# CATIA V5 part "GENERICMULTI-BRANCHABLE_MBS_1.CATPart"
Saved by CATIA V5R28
Part number: GENERICMULTI-BRANCHABLE_MBS_1
Revision: ---
Publications: "SegmentExtremity.1", "SegmentExtremity.2", "ElecLogTerm.1", "Flexible Curve.1", "Point.6", "SegmentExtremity.3", "SegmentExtremity.4", "ElecLogTerm.2", "Flexible Curve.2", "Point.10", "SegmentExtremity.5", "SegmentExtremity.6", "ElecLogTerm.3", "Flexible Curve.3", "Point.12", "SegmentExtremity.7", "SegmentExtremity.8", "ElecLogTerm.4", "Flexible Curve.4", "Point.20", "SegmentExtremity.9", "SegmentExtremity.10", "ElecLogTerm.5", "Flexible Curve.5", "Point.22", "SegmentExtremity.11", "SegmentExtremity.12", "ElecLogTerm.6", "Flexible Curve.6", "SegmentExtremity.13", "SegmentExtremity.14", "ElecLogTerm.7", "Flexible Curve.7", "Point.31", "SegmentExtremity.15", "SegmentExtremity.16", "ElecLogTerm.8", "Flexible Curve.8", "Point.47", "SegmentExtremity.17", "SegmentExtremity.18", "ElecLogTerm.9", "Flexible Curve.9", "Point.49", "SegmentExtremity.19", "SegmentExtremity.20", "ElecLogTerm.10", "Flexible Curve.10", "CPoint.52", "SegmentExtremity.21", "SegmentExtremity.22", "ElecLogTerm.11", "Flexible Curve.11", "Point.65", "SegmentExtremity.23", "SegmentExtremity.24", "ElecLogTerm.12", "Flexible Curve.12", "Point.70", "SegmentExtremity.25", "SegmentExtremity.26", "ElecLogTerm.13", "Flexible Curve.13", "SegmentExtremity.27", "SegmentExtremity.28", "ElecLogTerm.14", "Flexible Curve.14", "SegmentExtremity.29", "SegmentExtremity.30", "ElecLogTerm.15", "Flexible Curve.15", "Point.98", "SegmentExtremity.31", "SegmentExtremity.32", "ElecLogTerm.16", "Flexible Curve.16", "Point.104", "SegmentExtremity.33", "SegmentExtremity.34", "ElecLogTerm.17", "Flexible Curve.17", "Point.106", "SegmentExtremity.35", "SegmentExtremity.36", "ElecLogTerm.18", "Flexible Curve.18", "Point.109", "SegmentExtremity.37", "SegmentExtremity.38", "ElecLogTerm.19", "Flexible Curve.19", "Point.118", "SegmentExtremity.39", "SegmentExtremity.40", "ElecLogTerm.20", "Flexible Curve.20", "Point.122", "SegmentExtremity.41", "SegmentExtremity.42", "ElecLogTerm.21", "Flexible Curve.21", "Point.127", "SegmentExtremity.43", "SegmentExtremity.44", "ElecLogTerm.22", "Flexible Curve.22", "Point.132", "SegmentExtremity.45", "SegmentExtremity.46", "ElecLogTerm.23", "Flexible Curve.23", "Point.137", "SegmentExtremity.47", "SegmentExtremity.48", "ElecLogTerm.24", "Flexible Curve.24", "SegmentExtremity.49", "SegmentExtremity.50", "ElecLogTerm.25", "Flexible Curve.25", "SegmentExtremity.51", "SegmentExtremity.52", "ElecLogTerm.26", "Flexible Curve.26", "Point.146", "Point.175", "SegmentExtremity.53", "SegmentExtremity.54", "Flexible Curve.27", "Point.192", "SegmentExtremity.55", "SegmentExtremity.56", "ElecLogTerm.28", "Flexible Curve.28", "Point.205", "SegmentExtremity.57", "SegmentExtremity.58", "ElecLogTerm.29", "Flexible Curve.29", "Point.210", "SegmentExtremity.59", "SegmentExtremity.60", "ElecLogTerm.30", "Flexible Curve.30", "SegmentExtremity.61", "SegmentExtremity.62", "ElecLogTerm.31", "Flexible Curve.31", "SegmentExtremity.63", "SegmentExtremity.64", "ElecLogTerm.32", "Flexible Curve.32", "Point.222", "Point.227", "SegmentExtremity.65", "SegmentExtremity.66", "ElecLogTerm.33", "Flexible Curve.33", "Point.238", "SegmentExtremity.67", "SegmentExtremity.68", "ElecLogTerm.34", "Flexible Curve.34", "Point.240", "Point.245", "SegmentExtremity.69", "SegmentExtremity.70", "ElecLogTerm.35", "Flexible Curve.35", "Point.250", "SegmentExtremity.71", "SegmentExtremity.72", "ElecLogTerm.36", "Flexible Curve.36", "Point.258", "SegmentExtremity.73", "SegmentExtremity.74", "ElecLogTerm.37", "Flexible Curve.37", "Point.269", "SegmentExtremity.75", "SegmentExtremity.76", "ElecLogTerm.38", "Flexible Curve.38", "Point.276", "SegmentExtremity.77", "SegmentExtremity.78", "ElecLogTerm.39", "Flexible Curve.39", "Point.278", "Point.281", "SegmentExtremity.79", "SegmentExtremity.80", "ElecLogTerm.40", "Flexible Curve.40", "Point.286", "SegmentExtremity.81", "SegmentExtremity.82", "ElecLogTerm.41", "Flexible Curve.41", "Point.291", "SegmentExtremity.83", "SegmentExtremity.84", "ElecLogTerm.42", "Flexible Curve.42", "SegmentExtremity.85", "SegmentExtremity.86", "ElecLogTerm.43", "Flexible Curve.43", "SegmentExtremity.87", "SegmentExtremity.88", "ElecLogTerm.44", "Flexible Curve.44", "SegmentExtremity.89", "SegmentExtremity.90", "ElecLogTerm.45", "Flexible Curve.45", "SegmentExtremity.91", "SegmentExtremity.92", "ElecLogTerm.46", "Flexible Curve.46", "SegmentExtremity.93", "SegmentExtremity.94", "ElecLogTerm.47", "Flexible Curve.47", "Point.309", "SegmentExtremity.95", "SegmentExtremity.96", "ElecLogTerm.48", "Flexible Curve.48", "SegmentExtremity.97", "SegmentExtremity.98", "ElecLogTerm.49", "Flexible Curve.49", "CPoint.315", "SegmentExtremity.99", "SegmentExtremity.100", "ElecLogTerm.50", "Flexible Curve.50", "SegmentExtremity.101", "SegmentExtremity.102", "ElecLogTerm.51", "Flexible Curve.51", "SegmentExtremity.105", "SegmentExtremity.106", "ElecLogTerm.53", "Flexible Curve.53", "Point.329", "SegmentExtremity.107", "SegmentExtremity.108", "ElecLogTerm.54", "Flexible Curve.54", "SegmentExtremity.109", "SegmentExtremity.110", "ElecLogTerm.55", "Flexible Curve.55", "Point.358", "BCPRPoint.1", "BCPRPoint.2", "BCPRPoint.3", "BCPRPoint.4", "BCPRPoint.5", "BCPRPoint.6", "BCPRPoint.7", "BCPRPoint.8", "BCPRPoint.9", "BCPRPoint.10", "BCPRPoint.11", "BCPRPoint.12", "BCPRPoint.13", "BCPRPoint.14", "BCPRPoint.15", "Point.376", "Point.377", "Point.378", "Point.379", "Point.380", "Point.381", "Point.382", "Point.383", "Point.384", "Point.385", "Point.386", "Point.387", "Point.388", "Point.389", "Point.390", "Point.391", "Point.392", "Point.393", "Point.394", "Point.395", "Point.396", "Point.397", "Point.398", "Point.399", "Point.400", "Point.401", "Point.402", "Point.403", "Point.404", "Point.405", "Point.406", "Point.407", "Point.408", "Point.409", "Point.410", "Point.411", "Point.412", "Point.413", "Point.414", "Point.415", "Point.416", "Point.417", "Point.418", "Point.419", "Point.420", "Point.421", "Point.422", "Point.423", "Point.424", "Point.425", "Point.426", "ElecLogTerm.58", "SegmentExtremity.117", "SegmentExtremity.118", "ElecLogTerm.59", "Flexible Curve.56", "Point.476", "SegmentExtremity.119", "SegmentExtremity.120", "ElecLogTerm.60", "Flexible Curve.57", "Point.478", "SegmentExtremity.121", "SegmentExtremity.122", "ElecLogTerm.61", "Flexible Curve.58", "Point.480", "SegmentExtremity.123", "SegmentExtremity.124", "ElecLogTerm.62", "Flexible Curve.59", "BCPRPoint_generated(BCP).1", "SegmentExtremity.125", "SegmentExtremity.126", "ElecLogTerm.63", "Flexible Curve.60", "BCPRPoint_generated(BCP).3", "Point.209", "Point.208", "BCPRPoint_generated(BCP).2"
Bounding box of the stored display mesh (mm): x 24808.223 to 28940.348, y -11503.752 to -2466.057, z 3790.857 to 5602.068
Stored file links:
  C:\Users\ajc8720\Documents\BOEING_WORK\0001-2CES\004-AP242\Boeing-Generic_Harness_R3\GENERICMULTI-BRANCHABLE_MBS_1.CATPart
  C:\Users\ajc8720\Documents\BOEING_WORK\0001-2CES\004-AP242\Boeing-Generic_Harness_R3\GENERICBUNDLE_GBN_1.CATProduct
  C:\Users\ajc8720\Documents\BOEING_WORK\0001-2CES\004-AP242\Boeing-Generic_Harness_R3\GENERICMULTI-BRANCHABLE_MBS_2.CATPart
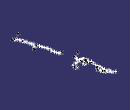
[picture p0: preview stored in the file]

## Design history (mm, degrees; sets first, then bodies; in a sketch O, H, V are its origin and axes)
Sketch1 on {plane type Normal, RefPoint {point type OnCurve, Real 0.5}}, origin (24974.0327, -3716.1791, 3931.1718), H (0.9925, -0.0197, 0.1205), V (0, -0.987, -0.1609)
  circle A1 centre (0, 0) radius 3.429
  point P1 (0, 0)
  reference projected point E1 (0, 0) from {point type OnCurve, Real 0.5}
  radius A1 = 3.429
  distance E1 P1 = 0
ElecRouteBody1
EhiBundleSegmentBody1
Sketch2 on {plane type Normal, RefPoint {point type OnCurve, Real 0.5}}, origin (24996.1011, -3716.6292, 3825.5253), H (0.0885, -0.5472, 0.8323), V (0, -0.8356, -0.5493)
  circle A1 centre (0, 0) radius 2.54
  point P1 (0, 0)
  reference projected point E1 (0, 0) from {point type OnCurve, Real 0.5}
  radius A1 = 2.54
  distance E1 P1 = 0
ElecRouteBody2
EhiBundleSegmentBody2
Sketch3 on {plane type Normal, RefPoint {point type OnCurve, Real 0.5}}, origin (24940.6374, -3680.2606, 3814.3878), H (0.1643, 0.9008, 0.4019), V (0, -0.4074, 0.9132)
  circle A1 centre (0, 0) radius 1.905
  point P1 (0, 0)
  reference projected point E1 (0, 0) from {point type OnCurve, Real 0.5}
  radius A1 = 1.905
  distance E1 P1 = 0
ElecRouteBody3
EhiBundleSegmentBody3
Sketch4 on {plane type Normal, RefPoint {point type OnCurve, Real 0.5}}, origin (25028.8374, -3731.3512, 3879.19), H (0.9078, -0.1558, -0.3893), V (0.0574, 0.9658, -0.2528)
  circle A1 centre (0.6341, 4.1659) radius 2.54
  point P1 (0.6341, 4.1659)
  reference projected point E1 (0.6341, 4.1659) from {point type OnCurve, Real 0.5}
  radius A1 = 2.54
  distance E1 P1 = 0
ElecRouteBody4
EhiBundleSegmentBody4
Sketch5 on {plane type Normal, RefPoint {point type OnCurve, Real 0.5}}, origin (24880.8569, -3717.6101, 3832.7739), H (1, 0, 0), V (0, -0.9945, 0.1045)
  circle A1 centre (0, 0) radius 2.54
  point P1 (0, 0)
  reference projected point E1 (0, 0) from {point type OnCurve, Real 0.5}
  radius A1 = 2.54
  distance E1 P1 = 0
ElecRouteBody5
EhiBundleSegmentBody5
Sketch6 on {plane type Normal, RefPoint {point type OnCurve, Real 0.5}}, origin (24877.0707, -3718.2397, 3795.6193), H (0.9998, -0.0172, -0.0118), V (0, 0.567, -0.8237)
  circle A1 centre (0, 0) radius 1.905
  point P1 (0, 0)
  reference projected point E1 (0, 0) from {point type OnCurve, Real 0.5}
  radius A1 = 1.905
  distance E1 P1 = 0
ElecRouteBody6
EhiBundleSegmentBody6
Sketch7 on {plane type Normal, RefPoint {point type OnCurve, Real 0.5}}, origin (24922.1033, -3327.3549, 4062.2802), H (0.9868, -0.034, -0.1586), V (0.0128, -0.9584, 0.2852)
  circle A1 centre (-0.0093, -0.0015) radius 6.2865
  point P1 (-0.0093, -0.0015)
  reference projected point E1 (-0.0093, -0.0015) from {point type OnCurve, Real 0.5}
  radius A1 = 6.2865
  distance E1 P1 = 0
ElecRouteBody7
EhiBundleSegmentBody7
Sketch8 on {plane type Normal, RefPoint {point type OnCurve, Real 0.5}}, origin (25104.099, -3784.957, 3887.1393), H (0.9158, 0.395, 0.0731), V (0, -0.1819, 0.9833)
  circle A1 centre (0, 0) radius 6.2865
  point P1 (0, 0)
  reference projected point E1 (0, 0) from {point type OnCurve, Real 0.5}
  radius A1 = 6.2865
  distance E1 P1 = 0
ElecRouteBody8
EhiBundleSegmentBody8
Sketch9 on {plane type Normal, RefPoint {point type OnCurve, Real 0.5}}, origin (24877.2621, -3716.0125, 3859.8032), H (0.8751, -0.0589, 0.4804), V (0, -0.9926, -0.1218)
  circle A1 centre (0, 0) radius 1.905
  point P1 (0, 0)
  reference projected point E1 (0, 0) from {point type OnCurve, Real 0.5}
  radius A1 = 1.905
  distance E1 P1 = 0
ElecRouteBody9
EhiBundleSegmentBody9
Sketch10 on {plane type Normal, RefPoint {point type OnCurve, Real 0.5}}, origin (25068.4213, -2719.6899, 4322.7599), H (0.7248, 0.6735, 0.1451), V (-0.0015, -0.2091, 0.9779)
  circle A1 centre (0.0002, 0) radius 10.795
  point P1 (0.0002, 0)
  reference projected point E1 (0.0002, 0) from {point type OnCurve, Real 0.5}
  radius A1 = 10.795
  distance E1 P1 = 0
ElecRouteBody10
EhiBundleSegmentBody10
Sketch11 on {plane type Normal, RefPoint {point type OnCurve, Real 0.5}}, origin (25149.9402, -3122.1503, 4269.3624), H (0.998, -0.0624, -0.0091), V (-0.0002, -0.1461, 0.9893)
  circle A1 centre (-0.4376, 0.1744) radius 10.795
  point P1 (-0.4376, 0.1744)
  reference projected point E1 (-0.4376, 0.1744) from {point type OnCurve, Real 0.5}
  radius A1 = 10.795
  distance E1 P1 = 0
ElecRouteBody11
EhiBundleSegmentBody11
Sketch12 on {plane type Normal, RefPoint {point type OnCurve, Real 0.5}}, origin (25166.8901, -3896.9029, 3882.9474), H (0.7778, 0.6111, -0.1466), V (0.0056, 0.2266, 0.974)
  circle A1 centre (0.8194, -0.468) radius 11.1125
  point P1 (0.8194, -0.468)
  reference projected point E1 (0.8194, -0.468) from {point type OnCurve, Real 0.5}
  radius A1 = 11.1125
  distance E1 P1 = 0
ElecRouteBody12
EhiBundleSegmentBody12
Sketch13 on {plane type Normal, RefPoint {point type OnCurve, Real 0.5}}, origin (24878.6032, -3724.4698, 3877.4644), H (0.5694, 0.6294, -0.5288), V (0.0035, -0.6452, -0.764)
  circle A1 centre (-1.7176, -0.5947) radius 1.905
  point P1 (-1.7176, -0.5947)
  reference projected point E1 (-1.7176, -0.5947) from {point type OnCurve, Real 0.5}
  radius A1 = 1.905
  distance E1 P1 = 0
ElecRouteBody13
EhiBundleSegmentBody13
Sketch14 on {plane type Normal, RefPoint {point type OnCurve, Real 0.5}}, origin (24872.7123, -3726.4812, 3889.1019), H (0.9735, 0.0632, -0.2196), V (0, -0.961, -0.2765)
  circle A1 centre (0, 0) radius 1.905
  point P1 (0, 0)
  reference projected point E1 (0, 0) from {point type OnCurve, Real 0.5}
  radius A1 = 1.905
  distance E1 P1 = 0
ElecRouteBody14
EhiBundleSegmentBody14
Sketch15 on {plane type Normal, RefPoint {point type OnCurve, Real 0.5}}, origin (25379.7377, -4011.427, 4382.97), H (0.9698, 0.2366, -0.0584), V (-0.0001, 0.2399, 0.9708)
  circle A1 centre (-0.0025, -0.0172) radius 10.795
  point P1 (-0.0025, -0.0172)
  reference projected point E1 (-0.0025, -0.0172) from {point type OnCurve, Real 0.5}
  radius A1 = 10.795
  distance E1 P1 = 0
ElecRouteBody15
EhiBundleSegmentBody15
Sketch16 on {plane type Normal, RefPoint {point type OnCurve, Real 0.5}}, origin (25298.9795, -4077.3191, 3915.4046), H (0.887, 0.4599, -0.0419), V (0.0034, 0.0842, 0.9964)
  circle A1 centre (3.3696, 1.071) radius 11.1125
  point P1 (3.3696, 1.071)
  reference projected point E1 (3.3696, 1.071) from {point type OnCurve, Real 0.5}
  radius A1 = 11.1125
  distance E1 P1 = 0
ElecRouteBody16
EhiBundleSegmentBody16
Sketch17 on {plane type Normal, RefPoint {point type OnCurve, Real 0.5}}, origin (25343.0812, -4267.5968, 3938.578), H (0.9508, -0.2973, 0.0872), V (0, -0.2813, -0.9596)
  circle A1 centre (0, 0) radius 5.5156
  point P1 (0, 0)
  reference projected point E1 (0, 0) from {point type OnCurve, Real 0.5}
  radius A1 = 5.5156
  distance E1 P1 = 0
ElecRouteBody17
EhiBundleSegmentBody17
Sketch18 on {plane type Normal, RefPoint {point type OnCurve, Real 0.5}}, origin (25220.9282, -4253.4289, 3922.4988), H (0.2661, 0.8516, -0.4516), V (-0.0109, 0.4711, 0.882)
  circle A1 centre (0.4487, 0.0773) radius 5.207
  point P1 (0.4487, 0.0773)
  reference projected point E1 (0.4487, 0.0773) from {point type OnCurve, Real 0.5}
  radius A1 = 5.207
  distance E1 P1 = 0
ElecRouteBody18
EhiBundleSegmentBody18
Sketch19 on {plane type Normal, RefPoint {point type OnCurve, Real 0.5}}, origin (25127.0757, -4194.8402, 3974.6536), H (0.9972, 0.0042, -0.0746), V (0, -0.9984, -0.0566)
  circle A1 centre (0, 0) radius 4.699
  point P1 (0, 0)
  reference projected point E1 (0, 0) from {point type OnCurve, Real 0.5}
  radius A1 = 4.699
  distance E1 P1 = 0
ElecRouteBody19
EhiBundleSegmentBody19
Sketch20 on {plane type Normal, RefPoint {point type OnCurve, Real 0.5}}, origin (25155.3324, -4251.9649, 3994.8839), H (0.8853, 0.4411, 0.1475), V (0.0275, 0.267, -0.9633)
  circle A1 centre (-0.0125, -1.3012) radius 4.7625
  point P1 (-0.0125, -1.3012)
  reference projected point E1 (-0.0125, -1.3012) from {point type OnCurve, Real 0.5}
  radius A1 = 4.7625
  distance E1 P1 = 0
ElecRouteBody20
EhiBundleSegmentBody20
Sketch21 on {plane type Normal, RefPoint {point type OnCurve, Real 0.5}}, origin (25225.9521, -4382.6463, 3976.8973), H (0.9058, 0.3736, -0.2001), V (0.0434, -0.5514, -0.8331)
  circle A1 centre (0.1521, -0.4281) radius 4.445
  point P1 (0.1521, -0.4281)
  reference projected point E1 (0.1521, -0.4281) from {point type OnCurve, Real 0.5}
  radius A1 = 4.445
  distance E1 P1 = 0
ElecRouteBody21
EhiBundleSegmentBody21
Sketch22 on {plane type Normal, RefPoint {point type OnCurve, Real 0.5}}, origin (25258.4813, -4409.6002, 4110.6492), H (1, -0.0028, 0.0003), V (-0.0028, -0.9945, 0.1045)
  circle A1 centre (-0.1173, 0.4811) radius 4.445
  point P1 (-0.1173, 0.4811)
  reference projected point E1 (-0.1173, 0.4811) from {point type OnCurve, Real 0.5}
  radius A1 = 4.445
  distance E1 P1 = 0
ElecRouteBody22
EhiBundleSegmentBody22
Sketch23 on {plane type Normal, RefPoint {point type OnCurve, Real 0.5}}, origin (25272.7768, -4402.1127, 4176.9601), H (0.3452, -0.8905, -0.2966), V (-0.0905, -0.3461, 0.9338)
  circle A1 centre (-0.0883, -7.5638) radius 3.81
  point P1 (-0.0883, -7.5638)
  reference projected point E1 (-0.0883, -7.5638) from {point type OnCurve, Real 0.5}
  radius A1 = 3.81
  distance E1 P1 = 0
ElecRouteBody23
EhiBundleSegmentBody23
Sketch24 on {plane type Normal, RefPoint {point type OnCurve, Real 0.5}}, origin (25293.8902, -4359.849, 4166.7271), H (0.9864, 0.161, 0.0342), V (0.0671, -0.5833, 0.8095)
  circle A1 centre (5.6529, 2.1812) radius 3.81
  point P1 (5.6529, 2.1812)
  reference projected point E1 (5.6529, 2.1812) from {point type OnCurve, Real 0.5}
  radius A1 = 3.81
  distance E1 P1 = 0
ElecRouteBody24
EhiBundleSegmentBody24
Sketch25 on {plane type Normal, RefPoint {point type OnCurve, Real 0.5}}, origin (25260.146, -4418.4617, 4183.4908), H (0.3181, -0.9478, 0.0231), V (0, 0.0244, 0.9997)
  circle A1 centre (0, 0) radius 1.905
  point P1 (0, 0)
  reference projected point E1 (0, 0) from {point type OnCurve, Real 0.5}
  radius A1 = 1.905
  distance E1 P1 = 0
ElecRouteBody25
EhiBundleSegmentBody25
Sketch26 on {plane type Normal, RefPoint {point type OnCurve, Real 0.5}}, origin (27135.7731, -8468.5501, 4977.5282), H (0.8995, 0.4119, 0.1458), V (-0.021, -0.2925, 0.956)
  circle A1 centre (0.1269, 3.209) radius 8.89
  point P1 (0.1269, 3.209)
  reference projected point E1 (0.1269, 3.209) from {point type OnCurve, Real 0.5}
  radius A1 = 8.89
  distance E1 P1 = 0
ElecRouteBody26
EhiBundleSegmentBody26
Sketch27 on {plane type Normal, RefPoint {point type OnCurve, Support {split Cutting (Point153; Point279)}, split-ratio-1 0.5}}, origin (27936.3689, -10212.7686, 5149.2041), H (0.9157, 0.401, 0.0271), V (-0.0571, 0.063, 0.9964)
  circle A1 centre (25.9839, -52.5194) radius 8.89
  point P1 (25.9839, -52.5194)
  reference projected point E1 (25.9839, -52.5194) from {point type OnCurve, Support {split Cutting (Point153; Point279)}, split-ratio-1 0.5}
  radius A1 = 8.89
  distance E1 P1 = 0
ElecRouteBody27
Sketch28 on {plane type Normal, RefPoint {point type OnCurve, Real 0.5}}, origin (28393.2611, -11186.8572, 5229.6274), H (0.8324, 0.5478, -0.0841), V (0.004, 0.1458, 0.9893)
  circle A1 centre (1.9129, -0.9935) radius 8.89
  point P1 (1.9129, -0.9935)
  reference projected point E1 (1.9129, -0.9935) from {point type OnCurve, Real 0.5}
  radius A1 = 8.89
  distance E1 P1 = 0
ElecRouteBody28
EhiBundleSegmentBody27
Sketch29 on {plane type Normal, RefPoint {point type OnCurve, Real 0.5}}, origin (28135.2468, -9421.3722, 4983.8556), H (0.8996, 0.3877, -0.2008), V (-0.064, 0.5721, 0.8177)
  circle A1 centre (-10.6864, -14.7208) radius 2.9667
  point P1 (-10.6864, -14.7208)
  reference projected point E1 (-10.6864, -14.7208) from {point type OnCurve, Real 0.5}
  radius A1 = 2.9667
  distance E1 P1 = 0
ElecRouteBody29
EhiBundleSegmentBody28
Sketch30 on {plane type Normal, RefPoint {point type OnCurve, Real 0.5}}, origin (27955.8204, -9580.6028, 5055.3472), H (0.4313, -0.8015, 0.4141), V (0.0096, 0.4631, 0.8863)
  circle A1 centre (0.0022, 0.0061) radius 4.2672
  point P1 (0.0022, 0.0061)
  reference projected point E1 (0.0022, 0.0061) from {point type OnCurve, Real 0.5}
  radius A1 = 4.2672
  distance E1 P1 = 0
ElecRouteBody30
EhiBundleSegmentBody29
Sketch31 on {plane type Normal, RefPoint {point type OnCurve, Real 0.5}}, origin (28139.325, -9513.4226, 4979.9224), H (0.5219, -0.1108, 0.8458), V (0, 0.9915, 0.1299)
  circle A1 centre (0, 0) radius 1.905
  point P1 (0, 0)
  reference projected point E1 (0, 0) from {point type OnCurve, Real 0.5}
  radius A1 = 1.905
  distance E1 P1 = 0
ElecRouteBody31
EhiBundleSegmentBody30
Sketch32 on {plane type Normal, RefPoint {point type OnCurve, Real 0.5}}, origin (25710.2697, -5343.8558, 4585.7173), H (0.8656, 0.4692, -0.1751), V (-0.0608, -0.2486, -0.9667)
  circle A1 centre (0.2141, -0.7248) radius 4.445
  point P1 (0.2141, -0.7248)
  reference projected point E1 (0.2141, -0.7248) from {point type OnCurve, Real 0.5}
  radius A1 = 4.445
  distance E1 P1 = 0
ElecRouteBody32
EhiBundleSegmentBody31
Sketch33 on {plane type Normal, RefPoint {point type OnCurve, Real 0.5}}, origin (25651.551, -5329.1759, 4407.7415), H (1, 0, 0), V (0, -0.9945, 0.1045)
  circle A1 centre (0, 0) radius 4.445
  point P1 (0, 0)
  reference projected point E1 (0, 0) from {point type OnCurve, Real 0.5}
  radius A1 = 4.445
  distance E1 P1 = 0
ElecRouteBody33
EhiBundleSegmentBody32
Sketch34 on {plane type Normal, RefPoint {point type OnCurve, Real 0.5}}, origin (26885.543, -5418.6743, 4308.1826), H (0.237, -0.0514, 0.9702), V (0, -0.9986, -0.0529)
  circle A1 centre (0, 0) radius 3.6385
  point P1 (0, 0)
  reference projected point E1 (0, 0) from {point type OnCurve, Real 0.5}
  radius A1 = 3.6385
  distance E1 P1 = 0
ElecRouteBody34
EhiBundleSegmentBody33
Sketch35 on {plane type Normal, RefPoint {point type OnCurve, Real 0.5}}, origin (26937.4509, -5540.9189, 4391.294), H (0.9975, -0.0458, 0.0544), V (0, 0.7646, 0.6445)
  circle A1 centre (0, 0) radius 3.6385
  point P1 (0, 0)
  reference projected point E1 (0, 0) from {point type OnCurve, Real 0.5}
  radius A1 = 3.6385
  distance E1 P1 = 0
ElecRouteBody35
EhiBundleSegmentBody34
Sketch36 on {plane type Normal, RefPoint {point type OnCurve, Real 0.5}}, origin (26949.5691, -5729.2329, 4501.9719), H (0.1607, 0.4709, 0.8674), V (0, 0.8789, -0.4771)
  circle A1 centre (0, 0) radius 3.175
  point P1 (0, 0)
  reference projected point E1 (0, 0) from {point type OnCurve, Real 0.5}
  radius A1 = 3.175
  distance E1 P1 = 0
ElecRouteBody36
EhiBundleSegmentBody35
Sketch37 on {plane type Normal, RefPoint {point type OnCurve, Real 0.5}}, origin (26425.8326, -5654.3351, 4615.7846), H (0.143, 0.1325, 0.9808), V (0, 0.991, -0.1339)
  circle A1 centre (0, 0) radius 7.62
  point P1 (0, 0)
  reference projected point E1 (0, 0) from {point type OnCurve, Real 0.5}
  radius A1 = 7.62
  distance E1 P1 = 0
ElecRouteBody37
EhiBundleSegmentBody36
Sketch38 on {plane type Normal, RefPoint {point type OnCurve, Real 0.5}}, origin (25922.1191, -5581.0705, 4639.1276), H (0.5485, 0.8236, 0.1443), V (0.0032, 0.1706, -0.9853)
  circle A1 centre (-0.1614, -0.1202) radius 7.62
  point P1 (-0.1614, -0.1202)
  reference projected point E1 (-0.1614, -0.1202) from {point type OnCurve, Real 0.5}
  radius A1 = 7.62
  distance E1 P1 = 0
ElecRouteBody38
EhiBundleSegmentBody37
Sketch39 on {plane type Normal, RefPoint {point type OnCurve, Real 0.5}}, origin (26104.4182, -5166.811, 4477.7803), H (0.9819, -0.186, 0.0355), V (0, 0.1875, 0.9823)
  circle A1 centre (0, 0) radius 3.6385
  point P1 (0, 0)
  reference projected point E1 (0, 0) from {point type OnCurve, Real 0.5}
  radius A1 = 3.6385
  distance E1 P1 = 0
ElecRouteBody39
EhiBundleSegmentBody38
Sketch40 on {plane type Normal, RefPoint {point type OnCurve, Real 0.5}}, origin (26094.1159, -5219.2861, 4487.7969), H (0.9819, -0.186, 0.0355), V (0, 0.1875, 0.9823)
  circle A1 centre (0, 0) radius 3.6385
  point P1 (0, 0)
  reference projected point E1 (0, 0) from {point type OnCurve, Real 0.5}
  radius A1 = 3.6385
  distance E1 P1 = 0
ElecRouteBody40
EhiBundleSegmentBody39
Sketch41 on {plane type Normal, RefPoint {point type OnCurve, Real 0.5}}, origin (26080.0781, -5370.3117, 4530.9454), H (0.9994, 0.0311, -0.0124), V (-0.0001, 0.3735, 0.9276)
  circle A1 centre (-1.766, -1.6351) radius 3.6385
  point P1 (-1.766, -1.6351)
  reference projected point E1 (-1.766, -1.6351) from {point type OnCurve, Real 0.5}
  radius A1 = 3.6385
  distance E1 P1 = 0
ElecRouteBody41
EhiBundleSegmentBody40
Sketch42 on {plane type Normal, RefPoint {point type OnCurve, Real 0.5}}, origin (26084.4248, -5568.6128, 4613.129), H (0.9975, -0.0657, 0.0267), V (0.0001, 0.378, 0.9258)
  circle A1 centre (0.5625, 0.1142) radius 3.6385
  point P1 (0.5625, 0.1142)
  reference projected point E1 (0.5625, 0.1142) from {point type OnCurve, Real 0.5}
  radius A1 = 3.6385
  distance E1 P1 = 0
ElecRouteBody42
EhiBundleSegmentBody41
Sketch43 on {plane type Normal, RefPoint {point type OnCurve, Real 0.5}}, origin (26823.1113, -5354.7859, 4255.6205), H (0.9002, 0.2156, 0.3785), V (-0.0041, 0.873, -0.4877)
  circle A1 centre (-0.5968, 0.9431) radius 3.175
  point P1 (-0.5968, 0.9431)
  reference projected point E1 (-0.5968, 0.9431) from {point type OnCurve, Real 0.5}
  radius A1 = 3.175
  distance E1 P1 = 0
ElecRouteBody43
EhiBundleSegmentBody42
Sketch44 on {plane type Normal, RefPoint {point type OnCurve, Real 0.5}}, origin (26821.66, -5344.5646, 4328.1943), H (0.6103, -0.0071, -0.7921), V (0, -1, 0.009)
  circle A1 centre (0, 0) radius 1.905
  point P1 (0, 0)
  reference projected point E1 (0, 0) from {point type OnCurve, Real 0.5}
  radius A1 = 1.905
  distance E1 P1 = 0
ElecRouteBody44
EhiBundleSegmentBody43
Sketch45 on {plane type Normal, RefPoint {point type OnCurve, Real 0.5}}, origin (26958.781, -5483.9474, 4351.6877), H (0.8033, -0.4236, -0.4187), V (0.0923, -0.6059, 0.7902)
  circle A1 centre (4.2812, 13.5801) radius 1.905
  point P1 (4.2812, 13.5801)
  reference projected point E1 (4.2812, 13.5801) from {point type OnCurve, Real 0.5}
  radius A1 = 1.905
  distance E1 P1 = 0
ElecRouteBody45
EhiBundleSegmentBody44
Sketch46 on {plane type Normal, RefPoint {point type OnCurve, Real 0.5}}, origin (26960.7672, -5486.283, 4341.4355), H (0.7577, -0.6286, -0.1756), V (0.0807, -0.1768, 0.9809)
  circle A1 centre (5.2877, 4.6116) radius 1.905
  point P1 (5.2877, 4.6116)
  reference projected point E1 (5.2877, 4.6116) from {point type OnCurve, Real 0.5}
  radius A1 = 1.905
  distance E1 P1 = 0
ElecRouteBody46
EhiBundleSegmentBody45
Sketch47 on {plane type Normal, RefPoint {point type OnCurve, Real 0.5}}, origin (25784.0878, -5534.4232, 4640.4976), H (0.9064, -0.2789, -0.3173), V (-0.0002, -0.7514, 0.6598)
  circle A1 centre (-8.4019, 0.0346) radius 3.81
  point P1 (-8.4019, 0.0346)
  reference projected point E1 (-8.4019, 0.0346) from {point type OnCurve, Real 0.5}
  radius A1 = 3.81
  distance E1 P1 = 0
ElecRouteBody47
EhiBundleSegmentBody46
Sketch48 on {plane type Normal, RefPoint {point type OnCurve, Real 0.5}}, origin (25717.4125, -5329.1271, 4352.2268), H (0.9393, 0.154, -0.3066), V (0, 0.8937, 0.4487)
  circle A1 centre (0, 0) radius 4.445
  point P1 (0, 0)
  reference projected point E1 (0, 0) from {point type OnCurve, Real 0.5}
  radius A1 = 4.445
  distance E1 P1 = 0
ElecRouteBody48
EhiBundleSegmentBody47
Sketch49 on {plane type Normal, RefPoint {point type OnCurve, Real 0.5}}, origin (25668.8211, -5340.8105, 4516.4463), H (0.8642, 0.4883, -0.1215), V (0, 0.2414, 0.9704)
  circle A1 centre (0, 0) radius 1.905
  point P1 (0, 0)
  reference projected point E1 (0, 0) from {point type OnCurve, Real 0.5}
  radius A1 = 1.905
  distance E1 P1 = 0
ElecRouteBody49
EhiBundleSegmentBody48
Sketch50 on {plane type Normal, RefPoint {point type OnCurve, Real 0.5}}, origin (25679.486, -5355.9342, 4556.5172), H (0.8736, 0.3501, 0.3379), V (0.0013, 0.6928, -0.7211)
  circle A1 centre (0, 0) radius 1.905
  point P1 (0, 0)
  reference projected point E1 (0, 0) from {point type OnCurve, Real 0.5}
  radius A1 = 1.905
  distance E1 P1 = 0
ElecRouteBody50
EhiBundleSegmentBody49
Sketch51 on {plane type Normal, RefPoint {point type OnCurve, Real 0.5}}, origin (25682.5652, -5370.1427, 4553.5001), H (0.964, -0.2409, 0.1126), V (0.0253, -0.3385, -0.9406)
  circle A1 centre (-4.4021, -1.7432) radius 1.905
  point P1 (-4.4021, -1.7432)
  reference projected point E1 (-4.4021, -1.7432) from {point type OnCurve, Real 0.5}
  radius A1 = 1.905
  distance E1 P1 = 0
ElecRouteBody51
EhiBundleSegmentBody50
Sketch52 on {plane type Normal, RefPoint {point type OnCurve, Real 0.5}}, origin (25657.6694, -5112.0454, 4591.8219), H (0.8724, 0.485, -0.0608), V (0.0438, 0.0463, 0.998)
  circle A1 centre (0.981, 1.3882) radius 10.795
  point P1 (0.981, 1.3882)
  reference projected point E1 (0.981, 1.3882) from {point type OnCurve, Real 0.5}
  radius A1 = 10.795
  distance E1 P1 = 0
ElecRouteBody52
EhiBundleSegmentBody51
Sketch53 on {plane type Normal, RefPoint {point type OnCurve, Real 0.5}}, origin (25772.7056, -5472.418, 4629.956), H (0.9947, -0.1028, 0.0066), V (0, 0.0642, 0.9979)
  circle A1 centre (0, 0) radius 10.795
  point P1 (0, 0)
  reference projected point E1 (0, 0) from {point type OnCurve, Real 0.5}
  radius A1 = 10.795
  distance E1 P1 = 0
ElecRouteBody53
EhiBundleSegmentBody52
Sketch54 on {plane type Normal, RefPoint {point type OnCurve, Real 0.5}}, origin (26022.8148, -5982.9735, 4488.8), H (0.8383, 0.5439, 0.0376), V (0, -0.0689, 0.9976)
  circle A1 centre (0, 0) radius 10.795
  point P1 (0, 0)
  reference projected point E1 (0, 0) from {point type OnCurve, Real 0.5}
  radius A1 = 10.795
  distance E1 P1 = 0
ElecRouteBody54
EhiBundleSegmentBody53
EhiBundleSegmentBody54
Sketch55 on {plane type Normal, RefPoint {point type OnCurve, Real 0.5}}, origin (28752.1918, -11443.4, 5276.2314), H (0.4239, -0.6404, -0.6404), V (0, 0.7071, -0.7071)
  circle A1 centre (59.5837, 0.003) radius 3.175
  point P1 (59.5837, 0.003)
  reference projected point E1 (59.5837, 0.003) from {point type OnCurve, Real 0.5}
  radius A1 = 3.175
  distance E1 P1 = 0
ElecRouteBody55
EhiBundleSegmentBody55
Sketch56 on {plane type Normal, RefPoint {point type OnCurve, Real 0.5}}, origin (28345.2675, -11448.2974, 5374.8665), H (0.8109, 0.1851, 0.5552), V (0, 0.9487, -0.3162)
  circle A1 centre (-47.496, 0.0012) radius 3.175
  point P1 (-47.496, 0.0012)
  reference projected point E1 (-47.496, 0.0012) from {point type OnCurve, Real 0.5}
  radius A1 = 3.175
  distance E1 P1 = 0
ElecRouteBody56
EhiBundleSegmentBody56
Sketch57 on {plane type Normal, RefPoint {point type OnCurve, Real 0.5}}, origin (25963.3263, -6329.0993, 4777.9487), H (0.7951, 0.1918, 0.5754), V (0, 0.9487, -0.3162)
  circle A1 centre (0, 0) radius 3.175
  point P1 (0, 0)
  reference projected point E1 (0, 0) from {point type OnCurve, Real 0.5}
  radius A1 = 3.175
  distance E1 P1 = 0
ElecRouteBody57
EhiBundleSegmentBody57
Sketch58 on {plane type Normal, RefPoint {point type OnCurve, Real 0.5}}, origin (28170.575, -9374.6759, 4947.0928), H (0.9632, -0.1857, 0.1945), V (0.2583, 0.4377, -0.8612)
  circle A1 centre (20.8051, -85.3963) radius 3.5052
  point P1 (20.8051, -85.3963)
  reference projected point E1 (20.8051, -85.3963) from {point type OnCurve, Real 0.5}
  radius A1 = 3.5052
  distance E1 P1 = 0
ElecRouteBody58
EhiBundleSegmentBody58
Sketch59 on {plane type Normal, RefPoint {point type OnCurve, Real 0.5}}, origin (28159.5165, -9424.7744, 4936.6988), H (0.9686, 0.2266, -0.1025), V (-0.0794, -0.1086, -0.9909)
  circle A1 centre (-18.748, -63.6992) radius 3.5052
  point P1 (-18.748, -63.6992)
  reference projected point E1 (-18.748, -63.6992) from {point type OnCurve, Real 0.5}
  radius A1 = 3.5052
  distance E1 P1 = 0
ElecRouteBody59
EhiBundleSegmentBody59
Set1 "ASSEMBLY_NOTES"
  Point1 "6.5": type OnCurve, Length 0
  Point2 "FER-GD3384": type OnCurve, Length 12.7
  Point3 "FER-GD4606": type OnCurve, Length 6.35
  Point4 "FER_GD26772": type OnCurve, Length 6.35
  Point5 "PINK373-33": type OnCurve, RefPoint Point236, Length 6.35
  Point6 "S4-1": type OnCurve, Length 50.8
  Point7 "S4-1(1)": type OnCurve, RefPoint Point276, Length 12.7
  Point8 "S4-D1614": type OnCurve, RefPoint Point178, Length 12.7
  Point9 "S4-D1628,S4-D1630": type OnCurve, Ratio 25.4
  Point10 "SD": type OnCurve, Length 58.6648
  Point11 "SM1": type OnCurve, RefPoint Point176, Length 76.2
  Point12 "SM2": type OnCurve, RefPoint Point47, Length 76.2
  Point13 "SR-DV815": type OnCurve, Length 63.5
  Point14 "TB2443_4": (381, 127, 127), relative to Point164
  Point15 "D12340P": (-381, 127, 381), relative to Point164
  Point16 "GB3223": (-381, 127, 381), relative to Point254
  Point17 "START_I-SL-P": type OnCurve, Length 127
  Point18 "END_I-SL-P": type OnCurve, Length 635
Set2
  Point19: (24976.1469, -3714.6858, 3897.737)
  Point20: (24976.1469, -3716.3319, 3882.0753)
  Point21: (24976.1475, -3718.6688, 3859.8381)
  Point22: (24976.1475, -3720.3149, 3844.1764)
  Point23: (24980.8255, -3719.5332, 3832.7779)
  Point24: (24993.5999, -3716.8262, 3825.875)
  Point25: (25011.553, -3718.793, 3831.6734)
  Point26: (24880.5727, -3712.8185, 3817.1898)
  Point27: (24885.7064, -3699.0199, 3813.1018)
  Point28: (24904.1921, -3689.1995, 3816.6014)
  Point29: (24918.4635, -3682.5781, 3815.9055)
  Point30: (25038.0499, -3721.1, 3889.375)
  Point31: (25064.664, -3701.1104, 3900.5305)
  Point32: (24880.8569, -3715.7922, 3850.0698)
  Point33: (24880.8569, -3716.456, 3843.7546)
  Point34: (24880.8569, -3718.1021, 3828.0929)
  Point35: (24877.1838, -3721.0652, 3794.0513)
  Point36: (25155.793, -3060.7793, 4277.4727)
  Point37: (25128.0077, -3122.3179, 4254.5)
  Point38: (25058.0468, -3168.7287, 4254.1114)
  Point39: (24944.5405, -3301.0676, 4207.9519)
  Point40: (24942.185, -3303.784, 4192.6199)
  Point41: (24933.1545, -3314.1983, 4133.8386)
  Point42: (24930.7991, -3316.9147, 4118.5066)
  Point43: (24925.6976, -3322.7978, 4085.3003)
  Point44: (24923.3422, -3325.5142, 4069.9682)
  Point45: (24903.5695, -3476.0387, 3926.1279)
  Point46: (24923.0073, -3517.4731, 3930.4828)
  Point47: (25016.8041, -3639.2352, 3890.0599)
  Point48: (25050.6417, -3680.0643, 3899.4198)
  Point49: (25145.342, -3868.1405, 3876.994)
  Point50: (24873.1218, -3718.3676, 3869.0639)
  Point51: (24817.7957, -2471.2433, 4376.5258)
  Point52: (24825.065, -2485.0308, 4374.2764)
  Point53: (24876.0634, -2558.4707, 4360.9365)
  Point54: (24885.6046, -2570.7778, 4358.5909)
  Point55: (25025.4666, -2684.1686, 4331.2346)
  Point56: (25037.8946, -2693.5486, 4328.8767)
  Point57: (25103.7044, -2784.8423, 4312.027)
  Point58: (25107.1071, -2800.0909, 4310.0519)
  Point59: (25157.6525, -3006.5802, 4282.8127)
  Point60: (25158.3503, -3022.2188, 4281.0959)
  Point61: (25151.7899, -3183.4586, 4260.4305)
  Point62: (25156.5905, -3883.3129, 3879.3642)
  Point63: (25186.4407, -3919.3356, 3887.5738)
  Point64: (25190.4469, -3924.1702, 3888.5182)
  Point65: (24873.0064, -3719.2075, 3870.7326)
  Point66: (25154.6402, -3195.7188, 4258.7428)
  Point67: (25158.2761, -3210.9109, 4256.7479)
  Point68: (25199.714, -3330.9613, 4259.6183)
  Point69: (25203.7112, -3345.9472, 4262.3467)
  Point70: (25252.4679, -3525.7757, 4299.7007)
  Point71: (25256.4753, -3540.7592, 4302.4276)
  Point72: (25304.8644, -3721.5171, 4335.3201)
  Point73: (25308.8718, -3736.5005, 4338.0469)
  Point74: (25357.0524, -3918.6947, 4366.5678)
  Point75: (25360.7572, -3933.7481, 4369.3371)
  Point76: (25387.5642, -4041.1928, 4390.9179)
  Point77: (25391.4489, -4055.924, 4394.9055)
  Point78: (25441.3326, -4241.4315, 4451.4127)
  Point79: (25445.2173, -4256.1627, 4455.4003)
  Point80: (25494.5933, -4443.3704, 4506.0753)
  Point81: (25498.478, -4458.1016, 4510.063)
  Point82: (25547.3733, -4646.1442, 4556.2434)
  Point83: (25551.258, -4660.8754, 4560.231)
  Point84: (25565.4091, -4831.4709, 4595.1421)
  Point85: (25229.2205, -3970.9617, 3899.3394)
  Point86: (25259.0706, -4006.9844, 3907.549)
  Point87: (25350.1812, -4222.7681, 3930.242)
  Point88: (25345.9067, -4255.5537, 3935.8064)
  Point89: (25338.3182, -4278.6924, 3942.4792)
  Point90: (25130.8233, -4202.5951, 3954.8406)
  Point91: (25131.3236, -4203.5528, 3951.8573)
  Point92: (25133.0468, -4208.8163, 3937.1153)
  Point93: (25146.0546, -4230.3804, 3914.775)
  Point94: (25174.0907, -4247.1189, 3918.3728)
  Point95: (25214.8264, -4251.8995, 3921.6758)
  Point96: (25304.7499, -4292.6, 3945.3379)
  Point97: (25132.9352, -4205.6458, 3992.0035)
  Point98: (25126.9627, -4194.9098, 3971.6736)
  Point99: (25179.6713, -4294.0028, 3976.2452)
  Point100: (25150.2509, -4242.4324, 3997.1004)
  Point101: (25135.5535, -4211.0996, 3993.8072)
  Point102: (25255.3136, -4411.9022, 4069.7158)
  Point103: (25220.0615, -4370.7445, 3971.8529)
  Point104: (25203.3761, -4335.7718, 3962.4318)
  Point105: (25258.4052, -4405.4135, 4151.6217)
  Point106: (25258.3627, -4406.1022, 4148.53)
  Point107: (25258.3627, -4410.4034, 4107.6074)
  Point108: (25293.8372, -4384.6306, 4166.3058)
  Point109: (26682.0816, -7461.9849, 4866.7341)
  Point110: (26776.0201, -7504.3673, 4842.392)
  Point111: (26791.7346, -7503.3789, 4842.1174)
  Point112: (26921.7007, -7554.1989, 4848.3789)
  Point113: (26927.8351, -7568.5808, 4850.2573)
  Point114: (27023.9456, -7772.2158, 4875.606)
  Point115: (27030.5336, -7786.4082, 4877.3875)
  Point116: (27089.669, -7926.5098, 4895.7871)
  Point117: (27096.257, -7940.7021, 4897.5686)
  Point118: (27215.297, -8154.3403, 4913.0692)
  Point119: (27221.9934, -8168.5162, 4914.5522)
  Point120: (27140.3352, -8244.3819, 4941.3683)
  Point121: (27126.0667, -8251.0352, 4941.7475)
  Point122: (27112.1084, -8420.75, 4984.6115)
  Point123: (27118.7668, -8434.9268, 4986.2497)
  Point124: (27181.3669, -8560.1471, 4956.7936)
  Point125: (27188.0236, -8574.3686, 4957.9925)
  Point126: (27196.3865, -8681.1735, 4951.2404)
  Point127: (27203.0432, -8695.395, 4952.439)
  Point128: (27288.7181, -8795.9032, 4962.0786)
  Point129: (27295.5014, -8810.0653, 4963.2708)
  Point130: (27353.4243, -8928.0977, 4999.9792)
  Point131: (27360.0759, -8942.3214, 5001.1798)
  Point132: (27453.5336, -9126.0997, 5025.3549)
  Point133: (27460.1903, -9140.3211, 5026.5549)
  Point134: (27552.074, -9358.9865, 5036.6227)
  Point135: (27558.4088, -9373.2977, 5038.3719)
  Point136: (27657.3847, -9561.4206, 5043.6187)
  Point137: (27664.4793, -9575.4029, 5045.0886)
  Point138: (27739.8042, -9625.157, 5057.6344)
  Point139: (27849.7222, -9693.1626, 5077.2761)
  Point140: (27856.0655, -9707.362, 5079.7542)
  Point141: (27839.8208, -9849.9134, 5103.672)
  Point142: (27842.5948, -9865.3169, 5105.4143)
  Point143: (27869.9832, -10040.1818, 5115.865)
  Point144: (27876.6414, -10054.365, 5117.4471)
  Point145: (27961.7814, -10202.4872, 5097.3004)
  Point146: (27968.0466, -10216.8793, 5098.57)
  Point147: (28072.759, -10470.043, 5156.7932)
  Point148: (28078.7342, -10484.5233, 5158.4106)
  Point149: (28141.4396, -10617.0716, 5158.5322)
  Point150: (28147.8827, -10630.81, 5159.9467)
  Point151: (28202.104, -10770.3528, 5183.4317)
  Point152: (28208.0792, -10784.8277, 5185.0975)
  Point153: (28222.834, -10823.2749, 5189.3316)
  Point154: (28291.3552, -10927.2887, 5209.7125)
  Point155: (28298.2516, -10941.3122, 5211.6573)
  Point156: (28358.6122, -11107.7821, 5216.1256)
  Point157: (28364.5853, -11122.221, 5218.0856)
  Point158: (28442.3737, -11258.7864, 5234.8589)
  Point159: (28449.0314, -11272.968, 5236.4576)
  Point160: (28532.5926, -11321.3428, 5193.4409)
  Point161: (28539.0102, -11335.0917, 5194.8697)
  Point162: (28569.3784, -11410.4016, 5201.378)
  Point163: (28575.0546, -11424.4712, 5202.8221)
  Point164: (28556.8149, -11500.0642, 5219.5676)
  Point165: (28128.5379, -9454.8672, 4992.7893)
  Point166: (28135.1216, -9468.5293, 4994.2924)
  Point167: (28128.1511, -9490.2148, 5000.481)
  Point168: (28017.3631, -9555.1098, 5038.2011)
  Point169: (28003.7408, -9560.7455, 5042.0649)
  Point170: (27907.1024, -9601.2634, 5064.3525)
  Point171: (27893.2654, -9607.1368, 5066.8619)
  Point172: (25783.0629, -5392.9552, 4621.2262)
  Point173: (25734.1647, -5392.7814, 4591.933)
  Point174: (25727.211, -5378.7292, 4590.4561)
  Point175: (25720.8566, -5364.8116, 4588.9923)
  Point176: (25714.1987, -5350.6184, 4587.5006)
  Point177: (25653.3903, -5318.8945, 4502.7856)
  Point178: (25651.5517, -5321.1617, 4483.9883)
  Point179: (25651.5517, -5322.8078, 4468.3266)
  Point180: (25651.5509, -5323.8171, 4458.7275)
  Point181: (25651.5509, -5325.4632, 4443.0658)
  Point182: (25651.551, -5330.959, 4390.7758)
  Point183: (25651.551, -5332.6051, 4375.1141)
  Point184: (25651.5507, -5333.6142, 4365.5149)
  Point185: (25651.5507, -5335.2603, 4349.8532)
  Point186: (25651.7137, -5325.7613, 4313.949)
  Point187: (26801.9027, -5370.0925, 4318.5511)
  Point188: (26802.7113, -5382.4602, 4321.3145)
  Point189: (26803.7238, -5397.945, 4323.9967)
  Point190: (26942.7957, -5439.8672, 4298.3816)
  Point191: (26943.8081, -5455.3519, 4301.0643)
  Point192: (26943.1066, -5485.3582, 4323.47)
  Point193: (26932.1617, -5581.7205, 4425.8312)
  Point194: (26929.5898, -5597.065, 4428.2668)
  Point195: (26932.0457, -5613.523, 4432.7493)
  Point196: (26974.7999, -5695.95, 4470.4)
  Point197: (26950.1365, -5729.277, 4501.8908)
  Point198: (26934.5931, -5728.0698, 4504.1146)
  Point199: (26925.0665, -5727.3299, 4505.4776)
  Point200: (26909.5231, -5726.1227, 4507.7014)
  Point201: (26802.3069, -5710.0015, 4553.0476)
  Point202: (26755.3525, -5702.7877, 4570.6695)
  Point203: (26739.898, -5700.752, 4572.9087)
  Point204: (26557.2892, -5662.1741, 4600.1063)
  Point205: (26541.7587, -5660.9588, 4602.4141)
  Point206: (26323.5543, -5647.9679, 4633.5648)
  Point207: (26308.0238, -5646.7526, 4635.8726)
  Point208: (26168.2366, -5635.9706, 4655.1588)
  Point209: (26152.7061, -5634.7554, 4657.4666)
  Point210: (26046.1182, -5627.7372, 4629.7496)
  Point211: (26021.0785, -5625.9724, 4627.0627)
  Point212: (26005.548, -5624.7572, 4629.3705)
  Point213: (25819.4085, -5525.4883, 4650.2427)
  Point214: (25804.2944, -5524.373, 4651.8482)
  Point215: (25801.1421, -5524.1465, 4652.1511)
  Point216: (26109.5416, -5140.7145, 4472.0078)
  Point217: (26105.8527, -5159.5044, 4476.3856)
  Point218: (26102.8707, -5174.6932, 4479.2849)
  Point219: (26099.2396, -5193.1887, 4482.0242)
  Point220: (26095.5502, -5211.9804, 4486.4024)
  Point221: (26092.5683, -5227.1692, 4489.3017)
  Point222: (26088.9371, -5245.6647, 4492.041)
  Point223: (26085.2482, -5264.4545, 4496.4188)
  Point224: (26082.2662, -5279.6434, 4499.3181)
  Point225: (26084.5052, -5492.4084, 4580.8241)
  Point226: (25770.1409, -5551.2089, 4621.388)
  Point227: (25682.7245, -5363.485, 4530.3607)
  Point228: (25683.0729, -5362.5839, 4546.0791)
  Point229: (25674.4606, -5351.8337, 4564.3144)
  Point230: (25683.0729, -5362.5839, 4546.0791)
  Point231: (25565.4091, -4831.4709, 4595.1421)
  Point232: (25559.5746, -4856.0872, 4597.9936)
  Point233: (25550.2732, -4898.2193, 4597.7881)
  Point234: (25669.5419, -5132.5925, 4594.3276)
  Point235: (25689.1933, -5174.4854, 4598.7304)
  Point236: (25759.8217, -5326.3255, 4613.9231)
  Point237: (25779.4731, -5368.2183, 4618.3262)
  Point238: (25772.8359, -5499.7493, 4629.2066)
  Point239: (25775.796, -5514.426, 4626.3626)
  Point240: (25763.9458, -5600.4123, 4619.7705)
  Point241: (25781.3432, -5637.4973, 4623.6682)
  Point242: (25840.3736, -5708.4024, 4577.7143)
  Point243: (25848.7381, -5717.6443, 4568.9462)
  Point244: (25901.2018, -5773.174, 4541.5763)
  Point245: (25921.8199, -5817.1271, 4546.1961)
  Point246: (25996.5384, -5925.4575, 4487.9068)
  Point247: (26000.3429, -5940.6553, 4489.5041)
  Point248: (26112.3803, -6125.2824, 4480.3558)
  Point249: (26116.1965, -6140.4784, 4481.9424)
  Point250: (26131.8724, -6183.6913, 4539.6276)
  Point251: (26130.6951, -6188.6504, 4554.528)
  Point252: (26099.4249, -6251.8496, 4639.9449)
  Point253: (26120.0428, -6295.8028, 4644.5646)
  Point254: (26179.5685, -6382.867, 4616.6475)
  Point255 to Point262: stored without definition
  Point263: (25155.793, -3060.7793, 4277.4727)
  Point264: (25155.793, -3060.7793, 4277.4727)
  Point265 to Point278: stored without definition
  Point279: (27739.8042, -9625.157, 5057.6344)
  Point280: (27739.8042, -9625.157, 5057.6344)
  Point281 to Point305: stored without definition
Set3
  Point306 to Point320 "BCPRPoint": linked copy from another document
  Point321: linked copy from another document
  Plane1: linked copy from another document
  Point322: linked copy from another document
  Plane2: linked copy from another document
  Point323: linked copy from another document
  Plane3: linked copy from another document
Body1 (main body)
